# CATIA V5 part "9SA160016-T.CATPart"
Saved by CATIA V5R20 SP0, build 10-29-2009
Part number: 9SA160016-T
Revision: ANY
Definition: UNKNOWN
Nomenclature: 9SA160016-T
Source: Unknown
Bounding box of the stored display mesh (mm): x -5.85 to 5.85, y 0 to 5.95, z -6 to 6
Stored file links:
  C:\Users\Utente\Desktop\IO LAVORO\3D X SITO CF\CUMSA\3D files SA\SA 160016\9SA160016-T.CATPart
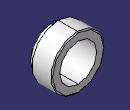
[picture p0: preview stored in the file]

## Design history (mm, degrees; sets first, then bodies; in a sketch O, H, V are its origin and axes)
Body1 "Chaflán1" (main body)
  Solid1: solid without history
